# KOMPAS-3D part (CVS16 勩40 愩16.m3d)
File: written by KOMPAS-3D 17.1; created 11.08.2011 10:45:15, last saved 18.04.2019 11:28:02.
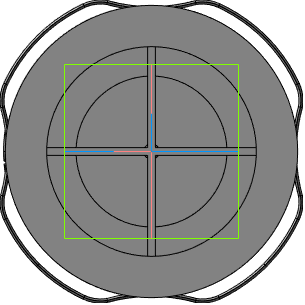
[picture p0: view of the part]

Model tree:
1. Плоскость XY
2. Плоскость ZX
3. Плоскость ZY
4. Ось X
5. Ось Y
6. Ось Z
7. Начало координат
8. Операция без истории:2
